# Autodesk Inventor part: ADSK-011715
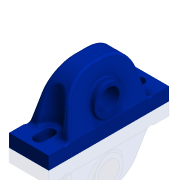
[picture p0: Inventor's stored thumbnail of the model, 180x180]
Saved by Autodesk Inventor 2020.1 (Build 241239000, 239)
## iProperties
Created: 1999-11
Part Number: ADSK-011715
Document SubType Name: Modeling
Designer: cmcgourin
Material: Générique
Density: 1 g/cm^3
Appearance: Blue(Flat)
Mass: 205.685 g
Surface Area: 316.811 cm^2
Volume: 205.685 cm^3
Control State: 0
Checked Out: False
Last Check In By: sspink
Last Check In Date: 1999-12-22
Master: False
Shininess: 0.0
Length Units: 11269
Angle Units: 11279
Time Units: 11290
Mass Units: 11283
Length Display Precision: 3
Angle Display Precision: 2
Compacted: True
Dimensions: 49,3x70,6x140 mm
Mass: 0,206 kg
DocNumber: ADSK-011715.ipt
Folder: 01 - Themengebiete\Simplification\01 - Packaging machine\
VDS_Category: 3D Komponenten
Density: 0.0
Volumn: 0.0
Area: 0.0
PropertySet Name: Model Information
Author: cmcgourin
Revision Number: -
Title: bearing block
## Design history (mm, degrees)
workpoint "Arbeitspunkt2"
workpoint "Arbeitspunkt3"
workaxis "Arbeitsachse3"
workaxis "Arbeitsachse4"
fillet "Rundung8" dims "d115" = 3
fillet "Rundung9" dims "d116" = 3
node "Solide1"
  node "Extrusion10" dims "d70" = 15, "d71" = 0
  node "Extrusion11" dims "d77" = 15.08125, "d78" = 0
  node "Extrusion12" dims "d79" = 55.5625, "d80" = -13 deg
  node "Fillet7" dims "d81" = 35
  node "Extrusion13" dims "d84" = 55.5625, "d85" = 0
  node "Extrusion14" dims "d88" = 55.5625, "d89" = 0
  node "Extrusion15" dims "d93" = 55.5625, "d94" = 0
workplane "Work Plane7"
sketch "Sketch13"
  geometry: L1 (117, 15)-(23, 15) reference; L2 (0, 0)-(140, 0) reference; L3 (0, 0)-(0, 15) reference; L4 (140, 0)-(0, 0) reference; C1 r 16.75 at (70, 36.5); 1 further point
  constraints: 1 centre point, 1 midpoint, 1 vertical alignment
  dimensions: "d83" = 33.5 diameter of C1; "d86" = 36.5 distance from line of C1.centre L2
sketch "Sketch14"
  geometry: C1 r 16.75 at (0, 0) reference; C2 r 12.5 at (0, 0)
  constraints: 1 centre point, 1 coincident
  dimensions: "d87" = 25 diameter of C2
sketch "Sketch10"
  geometry: L1 (-23, 70)-(23, 70); L2 (23, 70)-(23, -70); L3 (23, -70)-(-23, -70); L4 (-23, -70)-(-23, 70); 3 further points
  constraints: 8 end point, 2 midpoint, 2 parallel, 1 horizontal, 1 horizontal alignment, 1 perpendicular, 1 vertical alignment
  dimensions: "d95" = 46 distance of L2.end L3.end; "d96" = 140 distance of L3.end L1.start
sketch "Sketch11"
  geometry: L1 (23, -70)-(-23, -70) reference; L2 (23, 70)-(23, -70) reference; L3 (-23, 70)-(23, 70) reference; L4 (-23, -70)-(-23, 70) reference; L5 (6, -58)-(6, -46); L6 (-6, -46)-(-6, -58); L7 (-6, 46)-(-6, 58); L8 (6, 58)-(6, 46); L9 (0, 58)-(0, 46); L10 (-23, 0)-(23, 0); L11 (0, -46)-(0, -58); A1 r 6 centre (0, -58) between (-6, -58) and (6, -58); A2 r 6 centre (0, -46) between (6, -46) and (-6, -46); A3 r 6 centre (0, 46) between (-6, 46) and (6, 46); A4 r 6 centre (0, 58) between (6, 58) and (-6, 58); 5 further points
  constraints: 14 end point, 9 point on circle, 8 tangent, 6 midpoint, 4 centre point, 2 parallel, 2 vertical, 2 vertical alignment, 1 collinear
  dimensions: "d108" = 12 distance of L9.start L9.end; "d109" = 104 distance of point (0, -52) point (0, 52); "d110" = 52 distance from line of point (0, 52) L10 (= 0.5 x d109); "d111" = 12 distance of L5.start L5.end (= d108); "d112" = 12 distance between parallel lines of L7 L8
sketch "Sketch12"
  geometry: L1 (23, 70)-(23, -70) reference; L2 (-23, -70)-(-23, 70) reference; L3 (-23, -47)-(23, -47); L4 (-23, 47)-(23, 47); L5 (32.2, 0)-(-32.2, 0) reference
  constraints: 4 end point, 4 point on line, 2 perpendicular
  dimensions: "d113" = 94 distance between parallel lines of L4 L3; "d114" = 47 distance between parallel lines of L3 L5 (= 0.5 x d113)
node "Corps solides"
node "Corps surfaciques"
sketch "Sketch15"
  geometry: L1 (-12.7, 58)-(-12.7, 46); L2 (12.7, 46)-(12.7, 58); L3 (-12.7, -46)-(-12.7, -58); L4 (12.7, -58)-(12.7, -46); A1 r 6 centre (0, -58) between (-6, -58) and (6, -58) reference; A2 r 6 centre (0, 58) between (6, 58) and (-6, 58) reference; A3 r 12.7 centre (0, 46) between (-12.7, 46) and (12.7, 46); A4 r 12.7 centre (0, 58) between (12.7, 58) and (-12.7, 58); A5 r 12.7 centre (0, -58) between (-12.7, -58) and (12.7, -58); A6 r 12.7 centre (0, -46) between (12.7, -46) and (-12.7, -46); 4 further points; 4 other entities
  constraints: 8 end point, 8 point on circle, 4 centre point, 3 tangent, 9 other
  dimensions: "d91" = 12.7 distance from line of A1.centre L3; "d92" = 12.7 distance from line of A2.centre L1 (= d91)
other parameters: "d82" = 0
